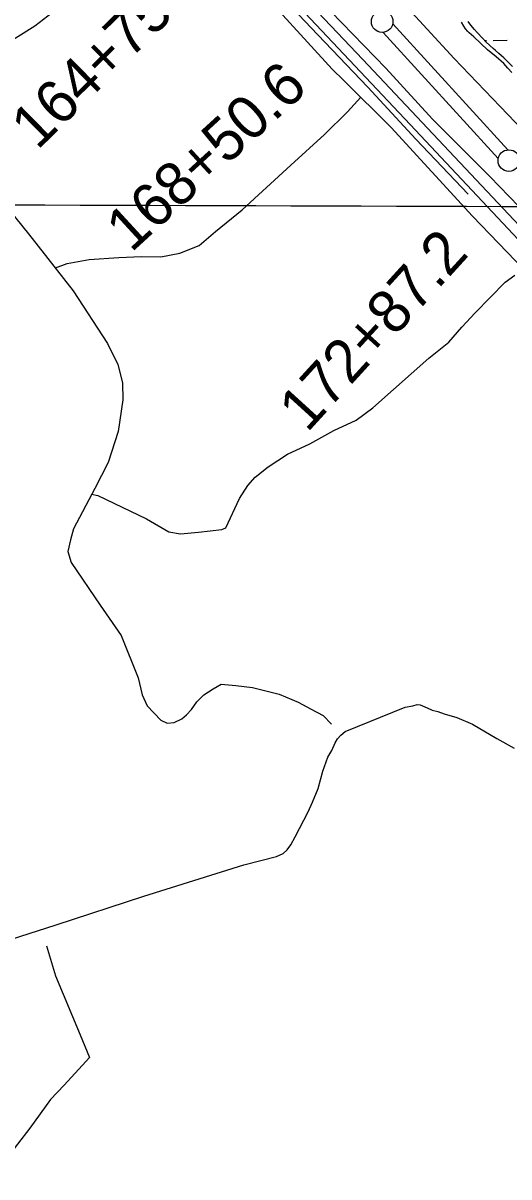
# Model space of a CAD drawing. Extents: x 3146026 to 3183936, y 897894 to 923344.
# Drawn here: x 3167435 to 3168564, y 907121 to 909801 of the extents above; entities that cross this region are included whole.
import ezdxf

# ---------------------------------------------------------------- set-up
doc = ezdxf.new("R2010")
doc.units = 0
for name, color, linetype in [('V-GRID-MAJR', 7, 'Continuous'), ('V-LEVE-TOET', 7, 'Continuous'), ('V-ROAD-CNTR', 7, 'Continuous'), ('V-SITE-VEGE', 7, 'Continuous'), ('V-SURV-IDEN', 7, 'Continuous'), ('V-SURV-LINE', 7, 'Continuous'), ('V-TOPO-SHOR', 7, 'Continuous'), ('V-WETL-SWMP', 7, 'Continuous')]:
    doc.layers.add(name, color=color, linetype=linetype)

msp = doc.modelspace()

# ---------------------------------------------------------------- linework, layer by layer
at = {"layer": 'V-GRID-MAJR'}
msp.add_spline([(3150267.842, 909437.3570000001), (3155490.4390000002, 909418.746), (3160713.04, 909400.895), (3165935.643, 909383.804), (3171158.249, 909367.4720000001), (3176380.857, 909351.9), (3181603.467, 909337.087), (3181603.468, 909337.087)], degree=3, dxfattribs=at)
at = {"layer": 'V-LEVE-TOET'}
for points in [[(3167399.001000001, 910846.9689999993), (3167518.594000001, 910700.0029999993), (3167625.774000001, 910577.7549999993), (3167717.815000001, 910478.0399999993), (3167816.768000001, 910378.8819999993), (3167935.045000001, 910257.1979999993), (3168065.359000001, 910117.7089999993), (3168182.910000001, 909994.3889999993), (3168311.219000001, 909856.3519999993), (3168436.616000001, 909718.6709999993), (3168578.407000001, 909570.4689999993), (3168708.697000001, 909439.5769999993)], [(3168519.134000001, 909445.0229999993), (3168386.287000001, 909577.7789999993), (3168278.021000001, 909696.2039999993), (3168150.087000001, 909827.8739999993), (3168010.481000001, 909975.7169999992), (3167883.277000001, 910105.3879999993), (3167731.0900000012, 910269.9449999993), (3167588.574000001, 910417.2369999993), (3167451.143000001, 910569.4489999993), (3167313.350000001, 910721.4799999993)], [(3168631.442000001, 909328.4489999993), (3168519.134000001, 909445.0229999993)]]:
    msp.add_lwpolyline(points, dxfattribs=at)
at = {"layer": 'V-ROAD-CNTR'}
for points in [[(3167456.132000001, 910490.7129999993), (3167508.688000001, 910430.7169999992), (3167595.445000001, 910336.0869999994), (3167695.146000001, 910226.1979999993), (3167793.565000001, 910120.6729999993), (3167889.978000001, 910017.6909999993), (3168000.058000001, 909901.2679999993), (3168119.434000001, 909773.9479999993), (3168235.527000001, 909652.2619999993), (3168347.436000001, 909531.6599999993), (3168469.173000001, 909403.4649999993)], [(3167909.5981440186, 910016.2059398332), (3168333.8092955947, 909565.8068406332), (3168788.269386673, 909082.0248081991), (3169046.431870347, 908808.0403561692)]]:
    msp.add_lwpolyline(points, dxfattribs=at)
at = {"layer": 'V-SITE-VEGE'}
msp.add_lwpolyline([(3168570.539000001, 909686.1999999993), (3168561.337000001, 909696.4359999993), (3168551.679000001, 909707.5989999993), (3168534.171000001, 909722.5089999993), (3168513.897000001, 909739.2879999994), (3168481.660000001, 909769.0919999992), (3168471.526000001, 909778.4069999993), (3168468.305000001, 909781.6649999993), (3168462.788000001, 909788.1759999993), (3168458.655000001, 909794.2169999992), (3168453.615000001, 909803.5029999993)], dxfattribs=at)
at = {"layer": 'V-SURV-LINE'}
for points in [[(3168293.599055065, 909799.8198230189), (3168560.938894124, 909506.6950716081)], [(3168538.7757294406, 909486.4764132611), (3168271.436227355, 909779.6007951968)]]:
    msp.add_lwpolyline(points, dxfattribs=at)
for centre in [(3168269.0491900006, 909804.4782599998), (3168563.325500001, 909481.8175499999)]:
    msp.add_circle(centre, 25, dxfattribs=at)
at = {"layer": 'V-TOPO-SHOR'}
for points in [[(3167210.8246144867, 910822.1103894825), (3167517.791679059, 910465.2725689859), (3167837.9666475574, 910124.2887636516), (3168224.607404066, 909716.7496611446), (3168612.8178704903, 909304.0529665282), (3169010.0653575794, 908878.3277529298), (3169146.001814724, 908729.7892284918), (3169231.012575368, 908622.6683569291), (3169303.3535869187, 908520.1444536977), (3169397.7377608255, 908380.373780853), (3169498.894082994, 908238.7194744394), (3169576.437532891, 908139.4695297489), (3169691.9005375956, 908023.0201828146), (3169813.440528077, 907910.6744956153), (3170173.2393000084, 907552.4464418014), (3170363.465104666, 907360.6963233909), (3170412.5968600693, 907315.9150195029), (3170466.2135140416, 907247.1396961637), (3170524.1580589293, 907180.8086301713), (3170574.3885929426, 907145.3782706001)], [(3167164.968467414, 909695.175963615), (3167183.1994247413, 909707.4869428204), (3167211.5213351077, 909714.4160987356), (3167322.005949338, 909732.8266243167), (3167372.707323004, 909747.694022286), (3167416.6813946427, 909766.1493024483), (3167462.6287923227, 909794.7852281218), (3167542.7283860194, 909857.4837489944), (3167622.917672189, 909923.5907671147), (3167738.133701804, 910024.5900816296), (3167792.355642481, 910076.0315556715)], [(3169924.781704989, 907727.000759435), (3169902.368990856, 907740.0022672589), (3169778.255801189, 907858.0767424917), (3169645.2482306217, 907991.8999318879), (3169538.5701678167, 908104.3440579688), (3169484.333533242, 908165.7612955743), (3169438.1480732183, 908218.692184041), (3169301.5772327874, 908413.633484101), (3169213.9934555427, 908544.1927529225), (3169166.012789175, 908607.5139905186), (3169120.99691644, 908665.5856567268), (3169072.798662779, 908720.6381324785), (3168900.8136003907, 908906.16822623), (3168830.42021989, 908982.4909716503), (3168639.259221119, 909186.1089541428), (3168479.1877300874, 909352.7079528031), (3168290.148318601, 909558.3387289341), (3168180.287874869, 909667.7636645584), (3168153.0607639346, 909694.3379024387), (3167850.461702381, 910026.0399315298)], [(3167510.93157977, 909232.4281199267), (3167537.6389339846, 909242.8106193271), (3167589.0354701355, 909251.6907239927), (3167657.3848000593, 909256.7138690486), (3167710.3061998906, 909258.7321329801), (3167755.4912115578, 909258.395832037), (3167799.196205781, 909266.6256204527), (3167843.9999786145, 909284.2063531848), (3167882.390373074, 909317.3047084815), (3167944.259009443, 909367.6922501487), (3168056.985935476, 909471.315206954), (3168135.605511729, 909542.5798171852), (3168188.9977512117, 909594.8958386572), (3168219.7414499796, 909629.0481263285)], [(3167402.364027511, 909367.8820905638), (3167447.7733620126, 909311.2607387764), (3167551.732711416, 909178.9125304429), (3167631.2271100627, 909056.5879599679), (3167655.535144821, 909008.1963049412), (3167666.343729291, 908965.2761656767), (3167667.0165144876, 908926.0336010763), (3167655.692335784, 908852.1454402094), (3167632.483262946, 908780.275451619), (3167601.896571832, 908719.6848871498), (3167552.5407685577, 908626.3323599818), (3167545.051080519, 908600.9480155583), (3167539.220794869, 908573.8145762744), (3167547.0693444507, 908548.0266157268), (3167614.3873026, 908449.0457484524), (3167662.8463644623, 908378.7007151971), (3167702.89634462, 908280.4373876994), (3167712.090372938, 908240.97059192), (3167723.347419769, 908215.0929388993), (3167754.8760651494, 908181.860136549), (3167770.034917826, 908174.6395259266), (3167786.2925491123, 908176.7698596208), (3167803.559266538, 908184.8426403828), (3167814.8835368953, 908193.9245072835), (3167826.297499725, 908206.4148714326), (3167838.7205486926, 908224.8476826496), (3167855.3369498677, 908240.6120053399), (3167877.021250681, 908254.5375406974), (3167895.207361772, 908265.1442712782), (3167929.247488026, 908262.5430979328), (3167968.355513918, 908258.103137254), (3168030.1793957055, 908241.9801363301), (3168074.0413975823, 908223.7716479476), (3168104.3142566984, 908207.6261780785), (3168132.053165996, 908192.4001018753), (3168151.1362934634, 908172.2855109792)], [(3167594.305956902, 908706.6675567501), (3167608.724800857, 908703.7299908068), (3167721.564071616, 908649.597834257), (3167773.6333929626, 908619.2353743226), (3167800.811678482, 908615.1093372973), (3167842.6778853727, 908618.2712260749), (3167896.5635251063, 908624.5276884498), (3167906.0490081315, 908628.5416557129), (3167937.68963162, 908696.7789158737), (3167957.243598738, 908726.9620825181), (3167973.9496923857, 908746.1349024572), (3168004.4243137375, 908770.0616983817), (3168049.5420102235, 908799.5721714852), (3168101.3421624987, 908823.7905137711), (3168156.7301969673, 908854.7361580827), (3168208.5303492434, 908878.9545003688), (3168247.6607524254, 908907.7698109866), (3168295.6711686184, 908949.9948794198), (3168377.744088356, 909022.8740458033), (3168423.915717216, 909060.0312145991), (3168453.8297147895, 909095.0580497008), (3168485.4031147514, 909128.3357899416), (3168554.626900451, 909198.9949301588), (3168577.2305949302, 909215.454415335)], [(3167301.420000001, 907639.1209999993), (3167511.854000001, 907706.8179999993), (3167715.775000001, 907772.7199999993), (3167947.771000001, 907845.5779999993), (3168023.451000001, 907865.0649999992), (3168039.132000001, 907872.2899999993), (3168048.729000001, 907880.9739999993), (3168057.322000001, 907891.8959999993), (3168066.977000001, 907910.9379999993), (3168097.365000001, 907968.6669999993), (3168107.650000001, 907991.5659999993), (3168120.217000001, 908022.9839999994), (3168131.618000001, 908063.7509999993), (3168142.765000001, 908095.7879999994), (3168152.198000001, 908111.5799999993), (3168160.015000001, 908129.2119999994), (3168165.758000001, 908138.7269999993), (3168173.118000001, 908147.2179999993), (3168182.916000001, 908155.8989999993), (3168322.182000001, 908211.8009999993), (3168340.082000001, 908215.5619999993), (3168350.252000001, 908217.9429999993), (3168357.158000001, 908217.7019999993), (3168373.370000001, 908210.7059999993), (3168385.529000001, 908205.1519999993), (3168398.310000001, 908202.2369999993), (3168412.906000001, 908196.6709999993), (3168442.922000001, 908187.7679999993), (3168478.594000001, 908172.7399999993), (3168535.696000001, 908139.5109999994), (3168575.792000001, 908116.7369999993)], [(3167489.529790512, 907657.6015098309), (3167510.720874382, 907587.9740163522), (3167567.6564247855, 907450.8942093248), (3167589.295971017, 907398.3092020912), (3167530.477062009, 907334.1979789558), (3167498.9036620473, 907300.9202387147), (3167451.095099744, 907233.961142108), (3167393.7113619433, 907159.5795809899), (3167377.6107383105, 907131.0109704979), (3167364.4253033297, 907083.6059326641), (3167343.5707953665, 907003.9995559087), (3167300.2247543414, 906879.7911685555), (3167288.833260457, 906835.749781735), (3167276.2756727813, 906812.2042246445), (3167225.058613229, 906745.3348205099), (3167215.999215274, 906725.1080681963), (3167198.485889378, 906675.2587730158), (3167180.5241011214, 906608.3669915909), (3167168.863529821, 906554.1001130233), (3167149.9598789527, 906516.2254044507), (3167109.6634736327, 906443.0996295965), (3167076.0270551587, 906396.2327465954), (3167062.034296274, 906382.9575274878)]]:
    msp.add_lwpolyline(points, dxfattribs=at)
at = {"layer": 'V-WETL-SWMP'}
for p, q in [((3168507.115084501, 909760.68498159), (3168511.3064164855, 909760.7267546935)), ((3168527.305621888, 909760.8862115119), (3168559.304032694, 909761.2051251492))]:
    msp.add_line(p, q, dxfattribs=at)
msp.add_lwpolyline([(3168572.1070000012, 909700.5259999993), (3168551.515000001, 909720.6829999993), (3168546.595000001, 909725.2229999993), (3168539.855000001, 909730.3049999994), (3168532.384000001, 909737.5689999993), (3168527.283000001, 909741.9259999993), (3168510.520000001, 909756.9969999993), (3168502.136000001, 909766.0779999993), (3168490.106000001, 909779.7019999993), (3168483.546000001, 909786.2389999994), (3168475.342000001, 909796.0489999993), (3168468.779000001, 909804.5879999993)], dxfattribs=at)

# ---------------------------------------------------------------- texts
at = {"layer": 'V-SURV-IDEN'}
for s, height, rotation, p in [('164+75.2', 100, 44.49083334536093, (3167468.3547491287, 909504.4527355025)), ('168+50.6', 100, 42.54527776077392, (3167686.1424484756, 909266.391251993)), ('172+87.2', 99.99999999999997, 47.68719386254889, (3168095.0151917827, 908848.1406300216))]:
    msp.add_text(s, height=height, rotation=rotation, dxfattribs=at).set_placement(p)

doc.saveas('drawing.dxf')
